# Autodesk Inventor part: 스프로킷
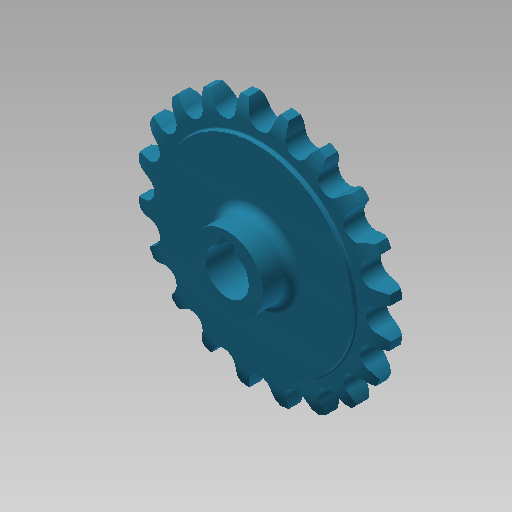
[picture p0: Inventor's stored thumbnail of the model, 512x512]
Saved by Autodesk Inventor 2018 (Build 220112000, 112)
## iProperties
Created: 2016-03
Part Number: 스프로킷
Material: 강철, 탄소
Document SubType Name: Modeling
Designer: mduedu
Density: 7.87 g/cm^3
Mass: 301.818 g
Surface Area: 124.882 cm^2
Volume: 38.3505 cm^3
Appearance: 터키옥색
Author: mduedu
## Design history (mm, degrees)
sketch "스케치1"
  geometry: L1 (0, 5)-(33.5, 5); L2 (33.5, 5)-(33.5, 4.1); L3 (34, 3.6)-(37.625, 3.6); L4 (44, 2)-(44, 0); L5 (44, 0)-(0, 0); L6 (0, 0)-(0, 5); L7 (0, -5)-(33.5, -5); L8 (33.5, -5)-(33.5, -4.1); L9 (34, -3.6)-(37.625, -3.6); L10 (44, -2)-(44, 0); L11 (0, 0)-(0, -5); A1 r 13.5 centre (37.625, -9.9) between (44, 2) and (37.625, 3.6); A2 r 13.5 centre (37.625, 9.9) between (37.625, -3.6) and (44, -2); A3 r 0.5 centre (34, 4.1) between (33.5, 4.1) and (34, 3.6); A4 r 0.5 centre (34, -4.1) between (34, -3.6) and (33.5, -4.1); 2 further points
  constraints: 22 end point, 8 point on circle, 6 symmetric about line, 5 tangent, 4 centre point, 4 parallel, 4 point on line, 1 equal radius, 1 horizontal, 1 perpendicular, 1 other
  dimensions: "d0" = 88 diameter of L4 L6; "d2" = 67 diameter of L2 L6; "d3" = 1.6 vertical distance of L4.start L3.end; "d4" = 3.6 distance from line of L4.end L3; "d5" = 5 distance between parallel lines of L5 L1; "d6" = 13.5 radius of A1; "d15" = 0.5 radius of A3
revolve "회전1" sketch "스케치1" stored, may be unused: angle "d7" = 90 deg
sketch "스케치2" dims "d8" = 73.24, "d11" = 88
  geometry: L1 (0, 0)-(0, 36.62); A1 r 40.59 centre (0, 0) between (-16.315, 37.167) and (0, 40.59); A2 r 3.97 centre (0, 40.59) between (-3.885, 39.775) and (0, 36.62); A3 r 12.7 centre (-16.315, 37.167) between (-3.885, 39.775) and (-5.404, 43.667); A4 r 12.7 centre (16.315, 37.167) between (5.404, 43.667) and (3.885, 39.775); A5 r 3.97 centre (0, 40.59) between (0, 36.62) and (3.885, 39.775); A6 r 44 centre (0, 0) between (5.404, 43.667) and (-5.404, 43.667); 2 further points
  constraints: 12 point on circle, 6 centre point, 4 coincident, 3 symmetric about line, 2 end point, 1 point on line, 1 tangent, 1 vertical, 1 vertical alignment, 7 other
  dimensions: "d10" = 81.18 diameter of A1; "d12" = 12.7 radius of A3
extrude "돌출1" cut sketch "스케치2" extent not by distance; stored distance "d13" = 10; taper "d14" = 0 deg
sketch "스케치3"
  geometry: C1 r 12.5 at (0, 0); 1 further point
  constraints: 1 centre point, 1 coincident
  dimensions: "d19" = 25 diameter of C1
extrude "돌출2" join sketch "스케치3" distance "d20" = 10; taper "d21" = 0 deg
fillet "모깎기1" dims "d22" = 3
sketch "스케치4"
  geometry: L1 (-2.5, 0)-(2.5, 0); L2 (2.5, 0)-(2.5, 9.8); L3 (2.5, 9.8)-(-2.5, 9.8); L4 (-2.5, 9.8)-(-2.5, 0); C1 r 7.5 at (0, 0); 2 further points
  constraints: 8 end point, 2 coincident, 2 parallel, 1 centre point, 1 horizontal, 1 midpoint, 1 perpendicular
  dimensions: "d23" = 15 diameter of C1; "d25" = 5 distance of L2.end L3.end; "d26" = 9.8 distance of L1.end L2.end
extrude "돌출3" cut sketch "스케치4" extent not by distance; stored distance "d27" = 8; taper "d28" = 0 deg
node "솔리드1"
pattern_circular "원형 패턴1" dims angle "d17" = 360 deg
